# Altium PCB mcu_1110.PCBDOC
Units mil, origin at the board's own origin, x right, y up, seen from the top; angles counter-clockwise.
Board outline 4331.71 x 2363.2 mil, 2 copper layers (TOP, BOTTOM), stack 10.4 mil thick; 53 components, 41 nets, 250 pads, 209 vias.
Unrouted connection lines stored in the file: 59.
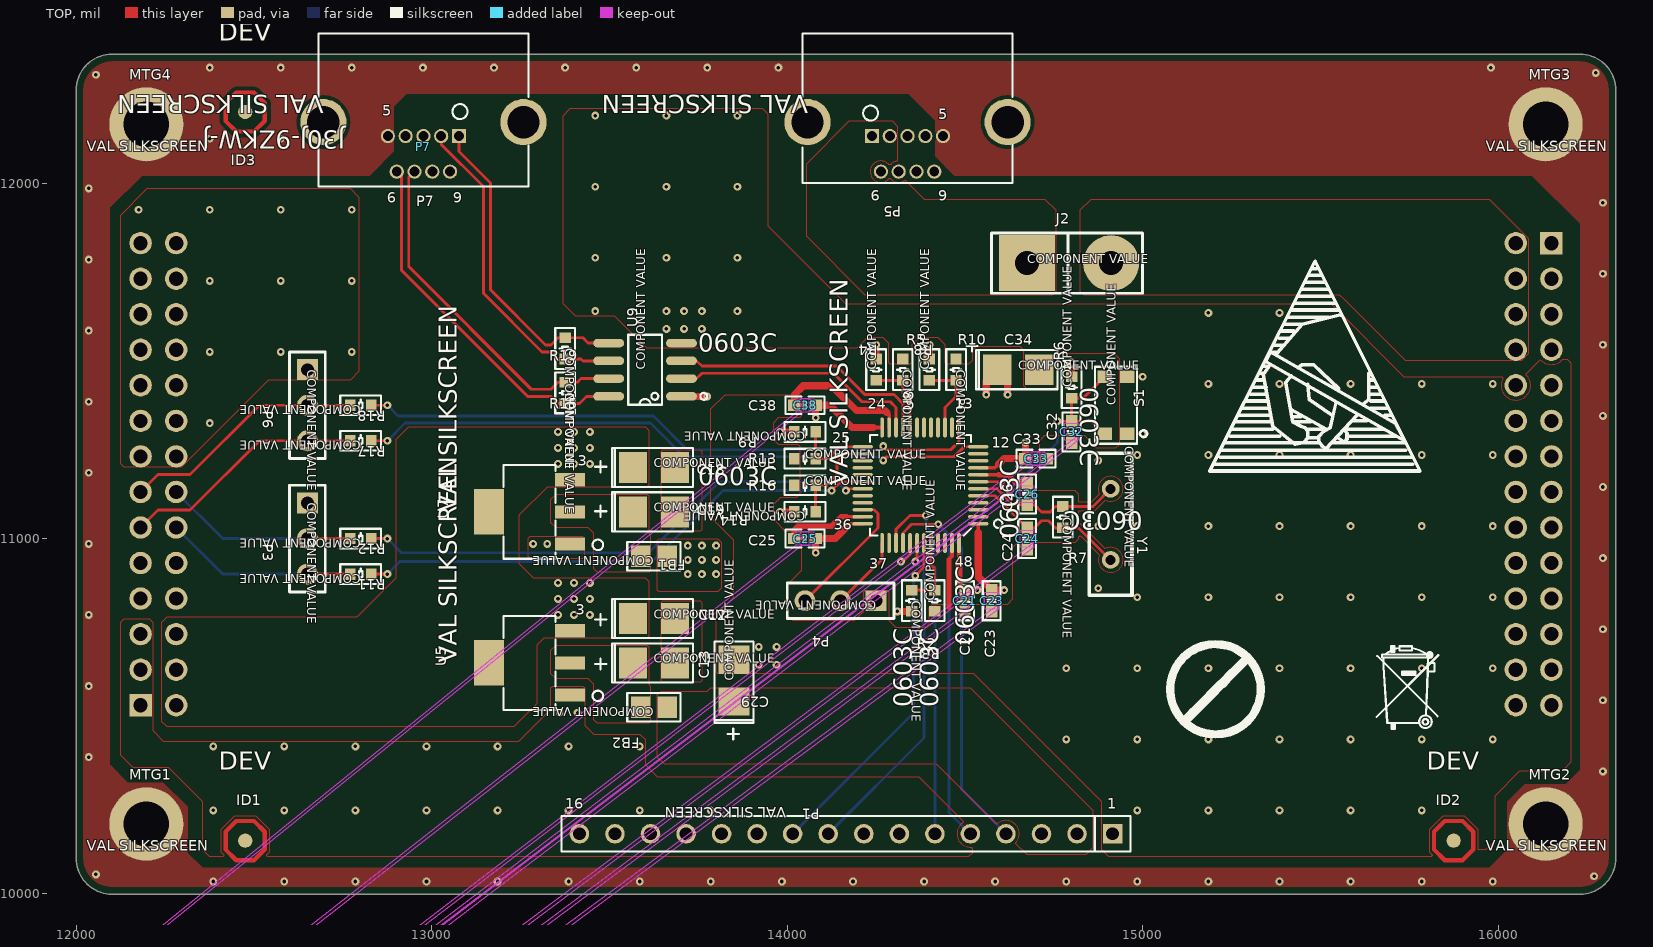
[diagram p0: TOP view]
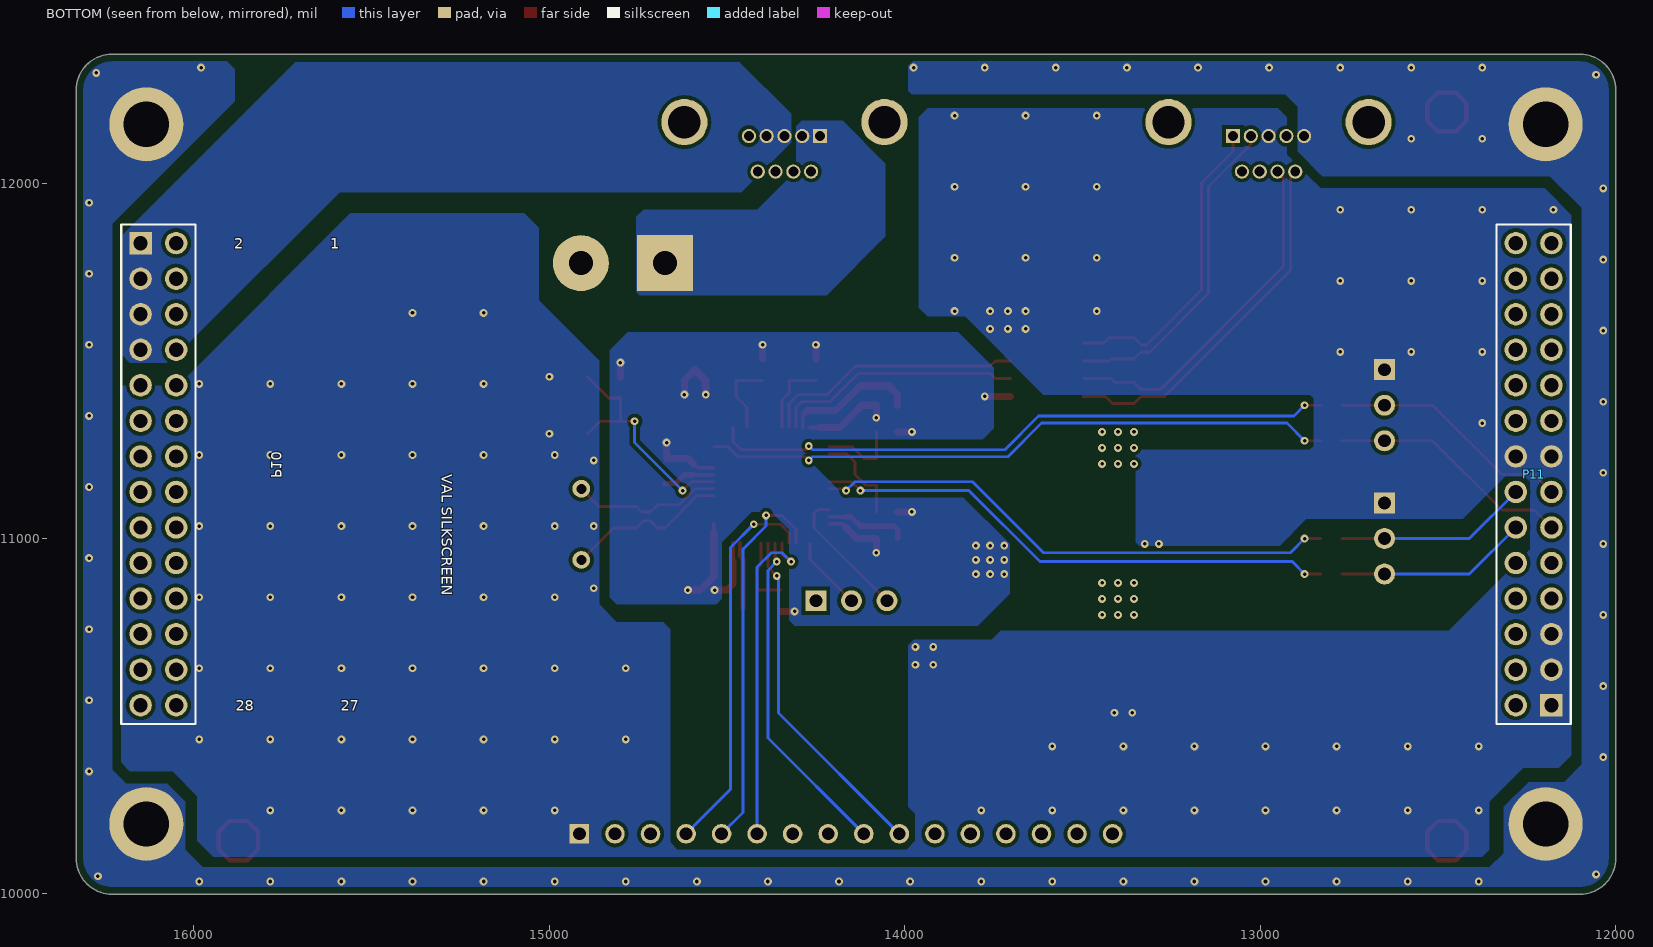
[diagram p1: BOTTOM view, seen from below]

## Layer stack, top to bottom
TOP: signal copper 1.2
Dielectric: core 8, FR-4, Dk 4.5
BOTTOM: signal copper 1.2

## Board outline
11999.5,10100 ccw(c12100,10100) 12100,9999.5 16230.71,9999.5 ccw(c16230.71,10100) 16331.21,10100 16331.21,12262.2 ccw(c16230.71,12262.2) 16230.71,12362.7 12100,12362.7 ccw(c12100,12262.2) 11999.5,12262.2

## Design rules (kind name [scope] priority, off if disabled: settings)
Clearance [All] p1: gap=10
PlaneConnect [All] p1: planeconnectstyle=Direct reliefexpansion=20 reliefentries=4 reliefconductorwidth=10 reliefairgap=10
PolygonConnect [All] p1: connectstyle=Direct reliefconductorwidth=10 reliefentries=4 polygonreliefangle="90 Angle"
RoomDefinition CompsKeepin1 [All vs False] p1: confinementstyle=ConfineIn formatcopy=TRUE lockcomponents=FALSE outline 12100,10040 12094.77,10040.23 12089.58,10040.91 12084.47,10042.04 12079.48,10043.62 12074.64,10045.62 12070,10048.04 12065.59,10050.85 12061.43,10054.04 12057.57,10057.57 12054.04,10061.43 12050.85,10065.59 12048.04,10070 12045.62,10074.64 12043.62,10079.48 12042.04,10084.47 12040.91,10089.58 12040.23,10094.77 12040,10100 12040,12262.2 12040.23,12267.43 12040.91,12272.62 12042.04,12277.73 12043.62,12282.73 12045.62,12287.56 12048.04,12292.2 12050.85,12296.62 12054.04,12300.77 12057.57,12304.63 12061.43,12308.17 12065.59,12311.35 12070,12314.17 12074.64,12316.58 12079.48,12318.59 12084.47,12320.16 12089.58,12321.29 12094.77,12321.98 12100,12322.2 16230.71,12322.2 16235.94,12321.98 16241.13,12321.29 16246.24,12320.16 16251.23,12318.59 16256.07,12316.58 16260.71,12314.17 16265.12,12311.35 16269.28,12308.17 16273.14,12304.63 16276.67,12300.77 16279.86,12296.62 16282.67,12292.2 16285.09,12287.56 16287.09,12282.73 16288.66,12277.73 16289.8,12272.62 16290.48,12267.43 16290.71,12262.2 16290.71,10100 16290.48,10094.77 16289.8,10089.58 16288.66,10084.47 16287.09,10079.48 16285.09,10074.64 16282.67,10070 16279.86,10065.59 16276.67,10061.43 16273.14,10057.57 16269.28,10054.04 16265.12,10050.85 16260.71,10048.04 16256.07,10045.62 16251.23,10043.62 16246.24,10042.04 16241.13,10040.91 16235.94,10040.23 16230.71,10040 12100,10040
RoutingVias [All] p1: holewidth=28 width=50 viastyle="Through Hole" minholewidth=28 minwidth=50 maxholewidth=28 maxwidth=50
SilkscreenOverComponentPads [All] p1: minsilkscreentomaskgap=10
SolderMaskExpansion [All] p1: expansion=4
TestPointUsage [All] p1: valid=0 allowmultiple=FALSE
Testpoint [All] p1: side=15 testpointundercomponent=TRUE minsize=40 maxsize=100 preferedsize=60 minholesize=0 maxholesize=40 preferedholesize=32 testpointgrid=1 style=1023 order=0123456789
Width [All] p1: maxlimit=10 minlimit=10 preferedwidth=10 impedancedriven=TRUE minimp=4.390000 maximp=4.390000 favimp=4.390000
22 further rules are at their usual default settings.

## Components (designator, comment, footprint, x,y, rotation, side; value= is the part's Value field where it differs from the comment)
C12 "3528T" 3528T 13607.28,10788.78 r0 top
C13 "3528T" 3528T 13607.28,10663.78 r0 top
C18 "3528T" 3528T 13607.28,11213.78 r0 top
C19 "3528T" 3528T 13607.28,11088.78 r0 top
C21 "0603C" 0603C#1 14500,10825 r90 top
C23 "0603C" 0603C#1 14575,10825 r90 top
C24 "0603C" 0603C#1 14675,11000 r90 top
C25 "0603C" 0603C#1 14050,11000 r0 top
C26 "0603C" 0603C#2 14675,11125 r270 top
C29 "3528T" 3528T 13836.22,10582.29 r90 top
C32 "0603C" 0603C#1 14800,11300 r90 top
C33 "0603C" 0603C#3 14700,11225 r180 top
C34 "3528T" 3528T 14632.28,11488.78 r0 top
C38 "0603C" 0603C#1 14050,11375 r0 top
FB1 "SM-7351-IND-0805" SM-7351-IND-0805 13625,10950 r180 top
FB2 "SM-7351-IND-0805" SM-7351-IND-0805 13625,10525 r180 top
J2 "28V" 28V 14787.5,11775 r0 top
MTG1 "MTGH200C125D_PL" MTGH200C125D_PL 12196.85,10196.85 r0 top
MTG2 "MTGH200C125D_PL" MTGH200C125D_PL 16133.86,10196.85 r0 top
MTG3 "MTGH200C125D_PL" MTGH200C125D_PL 16133.86,12165.35 r0 top
MTG4 "MTGH200C125D_PL" MTGH200C125D_PL 12196.85,12165.35 r0 top
P1 "HDR_16PIN" HDR_16PIN 14165.35,10169.29 r180 top
P3 "HDR1X3" HDR1X3 12650,11000 r270 top
P4 "HDR1X3" HDR1X3 14150,10825 r180 top
P5 "J30J-9TJW-J" J30J-9TJW-J 14338.75,12174.33 r180 top
P6 "HDR1X3" HDR1X3 12650,11375 r270 top
P7 "J30J-9ZKW-J" J30J-9ZKW-J 12976.55,12174.33 r180 top
P10 "HDR_14X2" HDR_14X2 16100.79,11181.5 r90 bottom
P11 "HDR_14X2" HDR_14X2 12229.92,11180.71 r270 bottom
R2 "R0603" R0603 14350,10825 r270 top
R3 "R0603" R0603 14415,10825 r90 top
R4 "R0603" R0603 14250,11475 r90 top
R5 "R0603" R0603 14325,11475 r270 top
R6 "R0603" R0603 14800,11425 r90 top
R7 "R0603" R0603 14775,11060 r270 top
R8 "R0603" R0603 14400,11475 r90 top
R9 "R0603" R0603 14050,11300 r180 top
R10 "R0603" R0603 14475,11475 r270 top
R11 "R0603" R0603 12800,10900 r180 top
R12 "R0603" R0603 12800,11000 r180 top
R13 "R0603" R0603 14050,11225 r0 top
R14 "R0603" R0603 14050,11075 r180 top
R15 "R0603" R0603 13375,11410 r270 top
R16 "R0603" R0603 14050,11150 r0 top
R17 "R0603" R0603 12800,11275 r180 top
R18 "R0603" R0603 12800,11375 r180 top
R19 "R0603" R0603 13375,11535 r270 top
S1 "SW4SMD_63X161LS" SW4SMD_63X161LS 14939.47,11375 r90 top
U5 "SOT-223-DCY" SOT-223-DCY 13272.58,10650.82 r90 top
U7 "SOT-223-DCY" SOT-223-DCY 13272.58,11075.82 r90 top
U8 "LQFP-48PIN" LQFP-48PIN 14375,11150 r90 top
U9 "8_SO" 8_SO 13630.52,11475 r90 top
Y1 "XTAL1" XTAL1 14910,11050 r270 top

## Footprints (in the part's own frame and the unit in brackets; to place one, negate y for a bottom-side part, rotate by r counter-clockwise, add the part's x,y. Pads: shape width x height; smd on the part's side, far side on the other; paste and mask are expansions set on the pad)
8_SO [mil] "8_SO"
  oval 24x87 smd: 1(-75,-71.84) 2(-25,-71.84) 3(25,-71.84) 4(75,-71.84) 5(75,132.87) 6(25,132.87) 7(-25,132.87) 8(-75,132.87)
  silkscreen extent -98,-145 98,78
28V [mil] "28V"
  rect 157x157 hole 67: 1(-112.5,0)
  round 157 hole 67: 2(123.72,0)
  silkscreen extent -212,-85 212,85
0603C#1 [mil] "0603C"
  rect 35x32 smd: 1(-30,0) 2(30,0)
  TOP keep-out region: -24,-19 -24,19 24,19 24,-19 -24,-19 -10825,14500
  TOP keep-out region: -10,-20 -10,20 10,20 10,-20 -10,-20 -10825,14500
  silkscreen extent -55,-25 55,25
0603C#2 [mil] "0603C"
  rect 35x32 smd: 1(-30,0) 2(30,0)
  TOP keep-out region: -24,-19 -24,19 24,19 24,-19 -24,-19 11125,-14675
  TOP keep-out region: -10,-20 -10,20 10,20 10,-20 -10,-20 11125,-14675
  silkscreen extent -55,-25 55,25
0603C#3 [mil] "0603C"
  rect 35x32 smd: 1(-30,0) 2(30,0)
  TOP keep-out region: -24,-19 -24,19 24,19 24,-19 -24,-19 14700,11225
  TOP keep-out region: -10,-20 -10,20 10,20 10,-20 -10,-20 14700,11225
  silkscreen extent -55,-25 55,25
3528T [mil] "3528T"
  rect 79x87 smd: 1(-41.34,-13.78) 2(76.77,-13.78)
  silkscreen extent -148,-69 128,41
HDR1X3 [mil] "HDR1X3"
  rect 59x59 hole 36: 1(-100,0)
  round 59 hole 36: 2(0,0) 3(100,0)
  silkscreen extent -150,-50 150,50
HDR_14X2 [mil] "HDR_14X2"
  rect 63x63 hole 40: 1(649.61,49.21)
  round 63 hole 40: 2(649.61,-50.79) 3(549.61,49.21) 4(549.61,-50.79) 5(449.61,49.21) 6(449.61,-50.79) 7(349.61,49.21) 8(349.61,-50.79) 9(249.61,49.21) 10(249.61,-50.79) 11(149.61,49.21) 12(149.61,-50.79) 13(49.61,49.21) 14(49.61,-50.79) 15(-50.39,49.21) 16(-50.39,-50.79) 17(-150.39,49.21) 18(-150.39,-50.79) 19(-250.39,49.21) 20(-250.39,-50.79) 21(-350.39,49.21) 22(-350.39,-50.79) 23(-450.39,49.21) 24(-450.39,-50.79) 25(-550.39,49.21) 26(-550.39,-50.79) 27(-650.39,49.21) 28(-650.39,-50.79)
  silkscreen extent -703,-105 702,104
HDR_16PIN [mil] "HDR_16PIN"
  rect 55x55 hole 36: 1(-750,0)
  round 55 hole 36: 2(-650,0) 3(-550,0) 4(-450,0) 5(-350,0) 6(-250,0) 7(-150,0) 8(-50,0) 9(50,0) 10(150,0) 11(250,0) 12(350,0) 13(450,0) 14(550,0) 15(650,0) 16(750,0)
  silkscreen extent -800,-50 800,50
J30J-9TJW-J [mil] "J30J-9TJW-J"
  rect 40x40 hole 28: 1(100.17,42.05)
  round 40 hole 28: 2(50.17,42.05) 3(0.17,42.05) 4(-49.83,42.05) 5(-99.83,42.05) 6(75.17,142.05) 7(25.17,142.05) 8(-24.83,142.05) 9(-74.83,142.05)
  round 130 hole 91: 10(281.67,2.67) 11(-281.33,2.67)
  silkscreen extent -295,-247 295,173
J30J-9ZKW-J [mil] "J30J-9ZKW-J"
  rect 40x40 hole 28: 1(-99.83,42.04)
  round 40 hole 28: 2(-49.83,42.04) 3(0.17,42.04) 4(50.17,42.04) 5(100.17,42.04) 6(-74.83,142.04) 7(-24.83,142.04) 8(25.17,142.04) 9(75.17,142.04)
  round 130 hole 91: 10(281.67,2.67) 11(-281.33,2.67)
  silkscreen extent -295,-247 295,183
LQFP-48PIN [mil] "LQFP-48PIN"
  oval 10x57 smd: 1(-108.27,-162.4) 2(-88.58,-162.4) 3(-68.9,-162.4) 4(-49.21,-162.4) 5(-29.53,-162.4) 6(-9.84,-162.4) 7(9.84,-162.4) 8(29.53,-162.4) 9(49.21,-162.4) 10(68.9,-162.4) 11(88.58,-162.4) 12(108.27,-162.4) 25(108.27,162.4) 26(88.58,162.4) 27(68.9,162.4) 28(49.21,162.4) 29(29.53,162.4) 30(9.84,162.4) 31(-9.84,162.4) 32(-29.53,162.4) 33(-49.21,162.4) 34(-68.9,162.4) 35(-88.58,162.4) 36(-108.27,162.4)
  oval 57x10 smd: 13(162.4,-108.27) 14(162.4,-88.58) 15(162.4,-68.9) 16(162.4,-49.21) 17(162.4,-29.53) 18(162.4,-9.84) 19(162.4,9.84) 20(162.4,29.53) 21(162.4,49.21) 22(162.4,68.9) 23(162.4,88.58) 24(162.4,108.27) 37(-162.4,108.27) 38(-162.4,88.58) 39(-162.4,68.9) 40(-162.4,49.21) 41(-162.4,29.53) 42(-162.4,9.84) 43(-162.4,-9.84) 44(-162.4,-29.53) 45(-162.4,-49.21) 46(-162.4,-68.9) 47(-162.4,-88.58) 48(-162.4,-108.27)
  silkscreen extent -142,-230 142,142
MTGH200C125D_PL [mil] "MTGH200C125D_PL"
  round 208 hole 128: 1(0,0)
R0603 [mil] "R0603"
  rect 30x32 smd: 1(-29.92,0) 2(29.92,0)
  silkscreen extent -57,-28 57,28
SM-7351-IND-0805 [mil] "SM-7351-IND-0805"
  rect 55x61 smd: 1(37.4,0) 2(-37.4,0)
  silkscreen extent -75,-40 75,40
SOT-223-DCY [mil] "SOT-223-DCY"
  rect 37x85 smd: 1(-91.37,-116.58) 2(-0.82,-116.58) 3(89.73,-116.58)
  rect 128x85 smd: 4(-0.82,111.75)
  silkscreen extent -133,-209 131,70
SW4SMD_63X161LS [mil] "SW4SMD_63X161LS"
  rect 35x40 smd: 1(-80.71,-17.03) 2(-80.71,45.97) 3(80.71,-17.03) 4(80.71,45.97)
  silkscreen extent -108,-74 108,74
XTAL1 [mil] "XTAL1"
  round 50 hole 28: 1(-90,0) 2(110,0)
  silkscreen extent -190,-60 210,60

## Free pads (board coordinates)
  round 40 smd: 1(12475,10150) 1(12475,12200) 1(15875,10150)

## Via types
v1: diameter 22, hole 10, TOP to BOTTOM, 209 vias

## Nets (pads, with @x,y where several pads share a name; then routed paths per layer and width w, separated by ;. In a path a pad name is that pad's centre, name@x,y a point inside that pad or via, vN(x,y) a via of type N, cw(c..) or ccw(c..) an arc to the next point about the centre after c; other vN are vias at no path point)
+3V3: C21.2 C23.2 C25.2 C33.2 C34.1 C38.2 FB1.2 R2.2 R4.2 R6.2 R8.2 R9.2 R14.2 U8.1 U8.9 U8.24 U8.36 U8.48 U9.1 | length 1515.6
  TOP w10: 14166.73,11031.73 14176.73,11041.73 U8.36 ; 14242.6,11312.4 U8.24 ; 14483.27,10935 U8.48 ; 14537.4,11017.4 U8.1 ; U8.9 14584.21,11199.21 14595,11210
  TOP w20: U9.1 v1(13775,11400) ; v1(13980,11075) R14.2 ; v1(13980,11300) R9.2 ; v1(14080,10960) C25.2 14135,11000 14166.73,11031.73 ; v1(14080,11340) C38.2 14120,11375 14182.6,11312.4 14242.6,11312.4 ; R4.2 v1(14250,11545) ; v1(14310,10795) 14349.92,10795 R2.2 ; R8.2 v1(14400,11545) ; 14483.27,10935 14483.27,10871.73 C21.2 v1(14535,10855) ; 14537.4,11017.4 14537.4,10892.6 C23.2 v1(14610,10855) ; v1(14560,11405) 14560,11444.06 C34.1 14620,11445.94 v1(14620,11405) ; 14595,11210 14610,11225 C33.2 v1(14670,11270) ; R6.2 v1(14800,11495)
  other v1: 13720,10900 13760,10900 13800,10900 13720,10940 13760,10940 13800,10940 13720,10980 13760,10980 13800,10980
BOOT0: R2.1 R3.2 U8.44 | length 202
  TOP w8: R2.1 R3.2 14415,10915 14404.53,10925.47 U8.44
EARTH: MTG1.1 MTG2.1 MTG3.1 MTG4.1 P5.5 P7.5
  other v1: 12385,10035 12585,10035 12785,10035 12985,10035 13185,10035 13385,10035 13585,10035 13785,10035 13985,10035 14185,10035 14385,10035 14585,10035 14785,10035 14985,10035 15185,10035 15385,10035 15585,10035 15785,10035 15985,10035 16270,10050 12055,10055 16295,10345 12035,10385 16295,10545 12035,10585 16295,10745 12035,10785 16295,10945 12035,10985 16295,11145 12035,11185 16295,11345 12035,11385 16295,11545 12035,11585 16295,11745 12035,11785 16295,11945 12035,11985 12375,12125 12575,12125 12055,12305 16275,12310 12375,12325 12575,12325 12775,12325 12975,12325 13175,12325 13375,12325 13575,12325 13775,12325 13975,12325 15980,12325
GND: C21.1 C23.1 C24.1 C25.1 C26.1 C29.2 C32.1 C33.1 C34.2 C38.1 P1.1 P3.1 P4.1 P6.1 P7.3 P11.1 P11.3 P11.5 P11.15 P11.16 R3.1 R5.1 R10.1 R13.1 R16.1 S1.1 S1.3 U5.1 U7.1 U8.8 U8.23 U8.35 U8.47 U9.4 | length 943.3
  TOP w10: 14166.42,11061.42 U8.35 ; 14280,11355 14286.42,11348.58 U8.23 ; 14455,10940 14455,10941.42 14463.58,10950 U8.47 ; U8.8 14594.53,11179.53
  TOP w15: C25.1 14020,11025 14030,11035 14125,11035 14151.42,11061.42 14166.42,11061.42 ; 14455,10805 14455,10930 14455,10940 ; 14594.53,11179.53 14620.47,11179.53 14645,11155 C26.1
  TOP w20: C38.1 14020,11405 14045,11430 14125,11430 14195,11360 14275,11360 14280,11355
  other v1: 12385,10235 12585,10235 12785,10235 12985,10235 13185,10235 13385,10235 13585,10235 13785,10235 14985,10235 15185,10235 15385,10235 15585,10235 15785,10235 12385,10415 12585,10415 12785,10415 12985,10415 13185,10415 13385,10415 13585,10415 14785,10435 14985,10435 15185,10435 15385,10435 15585,10435 15785,10435 15985,10435 13360,10510 13410,10510 14785,10635 14985,10635 15185,10635 15385,10635 15585,10635 15785,10635 15985,10635 13920,10645 13970,10645 13920,10695 13970,10695 14985,10835 15185,10835 15385,10835 15585,10835 15785,10835 15985,10835 14875,10860 13285,10985 13325,10985 14875,11035 14985,11035 15185,11035 15385,11035 15585,11035 15785,11035 15985,11035 14875,11220 14985,11235 15185,11235 15385,11235 15585,11235 15785,11235 15985,11235 15000,11295 12375,11325 15185,11435 15385,11435 15585,11435 15785,11435 15985,11435 15000,11455 12375,11525 12575,11525 12775,11525 13660,11590 13710,11590 13760,11590 15185,11635 15385,11635 13460,11640 13660,11640 13710,11640 13760,11640 13860,11640 12375,11725 12575,11725 12775,11725 13460,11790 13660,11790 13860,11790 12175,11925 12375,11925 12575,11925 12775,11925 13460,11990 13660,11990 13860,11990 13460,12190 13660,12190 13860,12190
NETC12_2: C12.2 C13.2
NETC18_2: C18.2 C19.2
NETP7_1: P7.1 R19.1 U9.5 | length 880.3
  TOP w8: P7.1 13076.38,12088.62 13165,12000 13165,11700 13320,11545 13335,11545 13354.92,11564.92 R19.1 13425,11564.92 13439.92,11550 U9.5
NETP7_2: P7.2 R19.2 U9.6 | length 922.8
  TOP w8: P7.2 13026.38,12108.62 13145,11990 13145,11690 13310,11525 13335,11525 13354.92,11505.08 R19.2 13419.92,11505.08 13425,11500 U9.6
NETP7_8: P7.8 R15.1 U9.7 | length 992
  TOP w8: P7.8 12935,12015.91 12935,11765 13280,11420 13335,11420 13354.92,11439.92 R15.1 13409.92,11439.92 13420,11450 U9.7
NETP7_9: P7.9 R15.2 U9.8 | length 1029.1
  TOP w8: P7.9 12915,12018.66 12915,11755 13270,11400 13335.08,11400 13355,11380.08 R15.2 13415.08,11380.08 13435,11400 U9.8
NRST: C32.2 R6.1 S1.2 S1.4 U8.7 | length 680.8
  TOP w8: U8.7 14600.16,11159.84 v1(14625,11135) ; v1(14760,11330) C32.2 ; S1.2 14857.79,11330 C32.2 ; S1.4 14832.87,11395.08 R6.1 C32.2
  BOTTOM w8: v1(14625,11135) 14760,11270 v1(14760,11330)
OLED_3V3: C29.1 FB2.2 P1.2
OLED_CS: P1.5 U8.39 | length 1086.1
  TOP w8: U8.39 14306.1,11026.1 14345,11065 v1(14390,11065)
  BOTTOM w8: v1(14390,11065) 14390,11035 14455,10970 14455,10229.65 P1.5
OLED_DC: P1.6 U8.41 | length 938.9
  TOP w8: v1(14320,10935) 14325,10935 14345.47,10955.47 U8.41
  BOTTOM w8: v1(14320,10935) 14345,10960 14375,10960 14415.35,10919.65 P1.6
OLED_RST: P1.4 U8.40 | length 1087
  TOP w8: U8.40 14325.79,11015.79 14350,11040 v1(14425,11040)
  BOTTOM w8: v1(14425,11040) 14490,10975 14490,10294.65 P1.4
OLED_SCLK: P1.9 U8.42 | length 942.5
  TOP w8: v1(14360,10935) 14365.16,10940.16 U8.42
  BOTTOM w8: P1.9 14385,10438.94 14385,10910 v1(14360,10935)
OLED_SDIN: P1.10 U8.43 | length 971.4
  TOP w8: v1(14360,10895) 14384.84,10919.84 U8.43
  BOTTOM w8: P1.10 14355,10508.94 14355,10890 v1(14360,10895)
PA5: R8.1 R10.2 U8.15 | length 220.6
  TOP w8: R8.1 R10.2 14475,11400 14443.9,11368.9 U8.15
PB2: R4.1 R5.2 U8.20 | length 216.2
  TOP w8: R4.1 R5.2 14325,11410 14345.47,11389.53 U8.20
PB12: R9.1 R13.2 U8.25 | length 221.5
  TOP w8: R9.1 R13.2 14115,11225 14148.27,11258.27 U8.25
PB13: R14.1 R16.2 U8.26 | length 264.9
  TOP w8: R14.1 R16.2 14110,11150 14140,11180 14140,11215 14163.58,11238.58 U8.26
PD0: C24.2 R7.2 U8.5 Y1.2 | length 463.9
  TOP w8: U8.5 14584.53,11120.47 C24.2 14695,11030 14715,11050 14735,11050 14754.92,11030.08 R7.2 14819.92,11030.08 Y1.2
PD1: C26.2 R7.1 U8.6 Y1.1 | length 426.5
  TOP w8: U8.6 14589.84,11140.16 14635,11095 C26.2 14695,11095 14715,11075 14740,11075 14754.92,11089.92 R7.1 14859.92,11089.92 Y1.1
RX_BD: P6.3 P11.11 R17.2 | length 690.4
  TOP w8: P11.11 12229.61,11080 12320,11080 12515,11275 P6.3 R17.2
RX_GPS: P3.3 P11.12 R11.2 | length 543.7
  TOP w8: P3.3 R11.2
  BOTTOM w8: P11.12 12411.81,10900 P3.3
SWCLK: P4.2 U8.37 | length 210.9
  TOP w8: P4.2 14266.73,10941.73 U8.37
SWDIO: P4.3 U8.34 | length 376.9
  TOP w8: P4.3 14255,11030 14255,11070 14243.9,11081.1 U8.34
TX_BD: P6.2 P11.13 R18.2 | length 690.4
  TOP w8: P11.13 12229.61,11180 12320,11180 12515,11375 P6.2 R18.2
TX_GPS: P3.2 P11.14 R12.2 | length 543.7
  TOP w8: P3.2 R12.2
  BOTTOM w8: P11.14 12411.81,11000 P3.2
UART1_RX: R12.1 U8.31 | length 1494.6
  TOP w8: R12.1 v1(12875,11000) ; v1(14165,11135) 14170.16,11140.16 U8.31
  BOTTOM w8: v1(12875,11000) 12915,10960 13609.64,10960 13809.64,11160 14140,11160 v1(14165,11135)
UART1_TX: R11.1 U8.30 | length 1490.3
  TOP w8: R11.1 v1(12875,10900) ; v1(14125,11135) 14149.84,11159.84 U8.30
  BOTTOM w8: v1(12875,10900) 12910,10935 13620,10935 13820,11135 v1(14125,11135)
UART2_RX: R18.1 U8.13 | length 1762.2
  TOP w8: R18.1 v1(12875,11375) ; v1(14270,11260) 14280,11250 14460,11250 14483.27,11273.27 U8.13
  BOTTOM w8: v1(12875,11375) 12905,11345 13623.28,11345 13718.28,11250 14260,11250 v1(14270,11260)
UART2_TX: R17.1 U8.12 | length 1787.5
  TOP w8: R17.1 v1(12875,11275) ; v1(14270,11220) 14280,11230 14470,11230 14498.27,11258.27 U8.12
  BOTTOM w8: v1(12875,11275) 12925,11325 13615,11325 13710,11230 14260,11230 v1(14270,11220)
UART3_RX: U8.22 U9.2 | length 706.3
  TOP w8: U9.2 13745,11450 13760,11465 14130,11465 14210,11385 14290,11385 14306.1,11368.9 U8.22
UART3_TX: U8.21 U9.3 | length 740.3
  TOP w8: U9.3 13745,11500 13760,11485 14138.29,11485 14218.28,11405 14300,11405 14325.79,11379.21 U8.21
VBUS+: J2.1 P5.1 P5.2
VBUS-: P5.3 P5.4 P10.1 P10.3 P10.5 P10.7
VBUSXX+: J2.2 P10.2 P10.4 P10.6 P10.8
VDD_3V3_1: C19.1 FB1.1 U7.2
VDD_3V3_2: C13.1 FB2.1 U5.2
VDD_12V: C12.1 C18.1 P11.2 P11.4 P11.6 U5.3 U7.3
  other v1: 13355,10785 13400,10785 13445,10785 13355,10830 13400,10830 13445,10830 13355,10875 13400,10875 13445,10875 13355,11210 13400,11210 13445,11210 13355,11255 13400,11255 13445,11255 13355,11300 13400,11300 13445,11300
pads on no net: P1.3 P1.7 P1.8 P1.11 P1.12 P1.13 P1.14 P1.15 P1.16 P5.6 P5.7 P5.8 P5.9 P5.10 P5.11 P7.4 P7.6 P7.7 P7.10 P7.11 P10.9 P10.10 P10.11 P10.12 P10.13 P10.14 P10.15 P10.16 P10.17 P10.18 P10.19 P10.20 P10.21 P10.22 P10.23 P10.24 P10.25 P10.26 P10.27 P10.28 P11.7 P11.8 P11.9 P11.10 P11.17 P11.18 P11.19 P11.20 P11.21 P11.22 P11.23 P11.24 P11.25 P11.26 P11.27 P11.28 U5.4 U7.4 U8.2 U8.3 U8.4 U8.10 U8.11 U8.14 U8.16 U8.17 U8.18 U8.19 U8.27 U8.28 U8.29 U8.32 U8.33 U8.38 U8.45 U8.46
copper on no net: | length 1109.1
  TOP w12: 12420,10125 12450,10095 12500,10095 12530,10125 12530,10175 12500,10205 12450,10205 12420,10175 12420,10125 ; 12420,12175 12450,12145 12500,12145 12530,12175 12530,12225 12500,12255 12450,12255 12420,12225 12420,12175 ; 15820,10125 15850,10095 15900,10095 15930,10125 15930,10175 15900,10205 15850,10205 15820,10175 15820,10125

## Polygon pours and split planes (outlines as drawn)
VDD_12V on TOP (solid): 26 vertices, not listed, extent 12240,10470 13610,11315
VDD_3V3_2 on TOP (solid): 13335,10620 13335,10685 13350,10700 13605,10700 13610,10695 13610,10590 13615,10585 13615,10485 13610,10480 13465,10480 13455,10490 13455,10590 13440,10605 13350,10605 13335,10620
VDD_3V3_1 on TOP (solid): 13335,11045 13335,11110 13350,11125 13605,11125 13610,11120 13610,11015 13615,11010 13615,10910 13610,10905 13465,10905 13455,10915 13455,11015 13440,11030 13350,11030 13335,11045
VBUSXX+ on TOP (solid): 16065,11500 15740,11500 15570,11670 15555,11685 14835,11685 14825,11695 14825,11925 14855,11955 15975,11955 16085,11845 16085,11520 16065,11500
VBUS+ on TOP (solid): 150 vertices, not listed, extent 14055,11685 14755,12175
OLED_3V3 on TOP (solid): 53 vertices, not listed, extent 13635,10110 14860,10580
NETC12_2 on TOP (solid): 13650,10825 13730,10825 13755,10825 13760,10820 13760,10600 13755,10595 13730,10595 13650,10595 13645,10600 13645,10820 13650,10825
NETC18_2 on TOP (solid): 13650,11250 13730,11250 13755,11250 13760,11245 13760,11025 13755,11020 13730,11020 13650,11020 13645,11025 13645,11245 13650,11250
GND on TOP (solid): 456 vertices, not listed, extent 13370,10105 16205,12210
GND on TOP (solid): 166 vertices, not listed, extent 12125,10105 14520,10775
GND on TOP (solid): 12125,11215 12125,11910 12200,11985 12660,11985 12770,11985 12795,11960 12795,11470 12770,11445 12710,11445 12540,11445 12295,11200 12160,11200 12135,11200 12125,11210 12125,11215
GND on TOP (solid): 13425,11005 13275,11005 13270,11000 13270,10950 13275,10945 13425,10945 13430,10950 13430,11000 13425,11005
+3V3 on TOP (solid): 13635,10855 13635,10995 13640,11000 13805,11000 13815,10990 13815,10860 13805,10850 13640,10850 13635,10855
EARTH on TOP (solid): 82 vertices, not listed, extent 12020,10020 16310.71,12342.2
VBUS+ on BOTTOM (solid): 137 vertices, not listed, extent 14055,11685 14755,12175
GND on BOTTOM (solid): 731 vertices, not listed, extent 12125,10105 16205,12210
+3V3 on BOTTOM (solid): 220 vertices, not listed, extent 13705,10755 14830,11580
EARTH on BOTTOM (solid): 110 vertices, not listed, extent 12020,10020 16310.71,12342.2
VBUS- on BOTTOM (solid): 159 vertices, not listed, extent 14320,11495 16200,12340
no net on Top Overlay (solid): 15343.11,10576.04 ccw(c15205.05,10576.04) 15205.05,10714.1 ccw(c15205.05,10576.04) 15066.98,10576.04 ccw(c15205.05,10576.04) 15205.05,10437.98 ccw(c15205.05,10576.04) 15343.11,10576.04
no net on Top Overlay (solid): 47 vertices, not listed, extent 15230.35,10516.09 15302.87,10640.37
no net on Top Overlay (solid): 33 vertices, not listed, extent 15119.06,10517.52 15212.4,10640.37
no net on Top Overlay (solid): 15343.11,10576.04 ccw(c15205.05,10576.04) 15205.05,10714.1 ccw(c15205.05,10576.04) 15066.98,10576.04 ccw(c15205.05,10576.04) 15205.05,10437.98 ccw(c15205.05,10576.04) 15343.11,10576.04
no net on Top Overlay (solid): 47 vertices, not listed, extent 15230.35,10516.09 15302.87,10640.37
no net on Top Overlay (solid): 33 vertices, not listed, extent 15119.06,10517.52 15212.4,10640.37

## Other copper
TOP:
  drawing of 49 lines, arcs and shapes, not listed
  text "MCU V1 ARTWORK TOP" at 13430,9595 h100
BOTTOM:
  drawing of 61 lines, arcs and shapes, not listed
  text "MCU V1 ARTWORK BOTTOM" at 15285,9590 h100

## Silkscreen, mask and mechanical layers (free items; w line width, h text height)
Top Overlay:
  drawing of 316 lines, arcs and shapes, not listed
  text "3" at 15747.01,21522.01 h125
  text "3" at 15747.01,21522.02 h125
  text "3" at 15747.01,21522.01 h125
  text "3" at 15747.01,21522.02 h125
  text "5" at 21396.61,21522.02 h125
  text "5" at 21396.61,21522.02 h125
  text "1" at 10116.41,21518.76 h125
  text "1" at 10116.41,21518.76 h125
  text "4" at 18567.2,21518.76 h125
  text "4" at 18567.2,21518.76 h125
  text "7" at 27049.48,21518.75 h125
  text "7" at 27049.48,21518.76 h125
  text "7" at 27049.48,21518.75 h125
  text "7" at 27049.48,21518.76 h125
  text "8" at 29974.28,21518.76 h125
  text "8" at 29974.28,21518.76 h125
  text "2" at 12922.74,21514.81 h125
  text "2" at 12922.74,21514.8 h125
  text "2" at 12922.74,21514.81 h125
  text "2" at 12922.74,21514.8 h125
  text "6" at 24225.48,21515.22 h125
  text "6" at 24225.48,21515.22 h125
  text "6" at 24225.48,21515.22 h125
  text "6" at 24225.48,21515.22 h125
  text "A" at 8574.09,20514.82 h125
  text "A" at 8574.09,20514.82 h125
  text "A" at 31369.36,20514.82 h125
  text "A" at 31369.36,20514.82 h125
  text "B" at 8581.96,18546.31 h125
  text "B" at 8581.96,18546.31 h125
  text "B" at 31377.24,18546.31 h125
  text "B" at 31377.24,18546.31 h125
  text "C" at 8593.5,16577.81 h125
  text "C" at 8593.5,16577.81 h125
  text "C" at 31388.78,16577.81 h125
  text "C" at 31388.78,16577.81 h125
  text "D" at 8577.48,14609.31 h125
  text "D" at 8577.48,14609.31 h125
  text "D" at 31372.75,14609.31 h125
  text "D" at 31372.75,14609.31 h125
  text "E" at 8589.83,12640.8 h125
  text "E" at 8589.83,12640.8 h125
  text "E" at 31385.11,12640.8 h125
  text "E" at 31385.11,12640.8 h125
  text "DEV" at 12400,12400 h51
  text "ID3" at 12435,12050 h30
  text "F" at 8589.83,10672.3 h125
  text "F" at 8589.83,10672.3 h125
  text "F" at 31385.11,10672.3 h125
  text "F" at 31385.11,10672.3 h125
  text "DEV" at 12400,10350 h51
  text "DEV" at 15800,10350 h51
  text "ID1" at 12450,10250 h30
  text "ID2" at 15825,10250 h30
  text "G" at 8586.04,8703.8 h125
  text "G" at 8586.04,8703.8 h125
  text "G" at 31381.31,8703.8 h125
  text "G" at 31381.31,8703.8 h125
  text "H" at 8581.96,6735.3 h125
  text "H" at 8581.96,6735.3 h125
  text "H" at 31377.24,6735.3 h125
  text "H" at 31377.24,6735.3 h125
  text "3" at 15747.01,5577.13 h125
  text "3" at 15747.01,5577.13 h125
  text "5" at 21396.61,5577.14 h125
  text "5" at 21396.61,5577.14 h125
  text "1" at 10116.41,5573.87 h125
  text "1" at 10116.41,5573.87 h125
  text "4" at 18567.2,5573.88 h125
  text "4" at 18567.2,5573.88 h125
  text "7" at 27049.48,5573.87 h125
  text "7" at 27049.48,5573.87 h125
  text "8" at 29874.28,5573.87 h125
  text "8" at 29874.28,5573.87 h125
  text "2" at 12922.74,5569.93 h125
  text "2" at 12922.74,5569.93 h125
  text "6" at 24225.48,5570.34 h125
  text "6" at 24225.48,5570.34 h125
Bottom Overlay:
  drawing of 13290 lines, arcs and shapes, not listed
  text "8" at 10033,21537.5 h125
  text "8" at 10033,21537.5 h125
  text "5" at 18682.66,21531.02 h125
  text "5" at 18682.66,21531.02 h125
  text "3" at 24332.26,21531.02 h125
  text "3" at 24332.26,21531.02 h125
  text "7" at 13029.79,21527.76 h125
  text "7" at 13029.79,21527.76 h125
  text "4" at 21512.07,21527.76 h125
  text "4" at 21512.07,21527.76 h125
  text "1" at 29962.86,21527.76 h125
  text "1" at 29962.86,21527.76 h125
  text "6" at 15853.79,21524.22 h125
  text "6" at 15853.79,21524.22 h125
  text "2" at 27156.53,21523.8 h125
  text "2" at 27156.53,21523.8 h125
  text "A" at 8709.91,20523.82 h125
  text "A" at 8709.91,20523.82 h125
  text "A" at 31505.18,20523.82 h125
  text "A" at 31505.18,20523.82 h125
  text "B" at 8702.03,18555.31 h125
  text "B" at 8702.03,18555.31 h125
  text "B" at 31497.31,18555.31 h125
  text "B" at 31497.31,18555.31 h125
  text "C" at 8690.49,16586.81 h125
  text "C" at 8690.49,16586.81 h125
  text "C" at 31485.77,16586.81 h125
  text "C" at 31485.77,16586.81 h125
  text "D" at 8706.52,14618.31 h125
  text "D" at 8706.52,14618.31 h125
  text "D" at 31501.79,14618.31 h125
  text "D" at 31501.79,14618.31 h125
  text "E" at 8694.16,12649.8 h125
  text "E" at 8694.16,12649.8 h125
  text "E" at 31489.44,12649.8 h125
  text "E" at 31489.44,12649.8 h125
  text "F" at 8694.16,10681.3 h125
  text "F" at 8694.16,10681.3 h125
  text "F" at 31489.44,10681.3 h125
  text "F" at 31489.44,10681.3 h125
  text "G" at 8697.96,8712.8 h125
  text "G" at 8697.96,8712.8 h125
  text "G" at 31493.23,8712.8 h125
  text "G" at 31493.23,8712.8 h125
  text "H" at 8702.03,6744.3 h125
  text "H" at 8702.03,6744.3 h125
  text "H" at 31497.31,6744.3 h125
  text "H" at 31497.31,6744.3 h125
  text "5" at 18682.66,5586.14 h125
  text "5" at 18682.66,5586.14 h125
  text "3" at 24332.26,5586.13 h125
  text "3" at 24332.26,5586.13 h125
  text "8" at 10204.99,5582.87 h125
  text "8" at 10204.99,5582.87 h125
  text "7" at 13029.79,5582.87 h125
  text "7" at 13029.79,5582.87 h125
  text "4" at 21512.07,5582.88 h125
  text "4" at 21512.07,5582.88 h125
  text "1" at 29962.86,5582.87 h125
  text "1" at 29962.86,5582.87 h125
  text "6" at 15853.79,5579.34 h125
  text "6" at 15853.79,5579.34 h125
  text "2" at 27156.53,5578.93 h125
  text "2" at 27156.53,5578.93 h125
DIMENSION:
  drawing of 8561 lines, arcs and shapes, not listed
  text "3" at 15747.01,21522.01 h125
  text "3" at 15747.01,21522.02 h125
  text "3" at 15747.01,21522.01 h125
  text "3" at 15747.01,21522.02 h125
  text "5" at 21396.61,21522.02 h125
  text "5" at 21396.61,21522.02 h125
  text "1" at 10116.41,21518.76 h125
  text "1" at 10116.41,21518.76 h125
  text "4" at 18567.2,21518.76 h125
  text "4" at 18567.2,21518.76 h125
  text "7" at 27049.48,21518.75 h125
  text "7" at 27049.48,21518.76 h125
  text "7" at 27049.48,21518.75 h125
  text "7" at 27049.48,21518.76 h125
  text "8" at 29974.28,21518.76 h125
  text "8" at 29974.28,21518.76 h125
  text "2" at 12922.74,21514.81 h125
  text "2" at 12922.74,21514.8 h125
  text "2" at 12922.74,21514.81 h125
  text "2" at 12922.74,21514.8 h125
  text "6" at 24225.48,21515.22 h125
  text "6" at 24225.48,21515.22 h125
  text "6" at 24225.48,21515.22 h125
  text "6" at 24225.48,21515.22 h125
  text "A" at 8574.09,20514.82 h125
  text "A" at 8574.09,20514.82 h125
  text "A" at 31369.36,20514.82 h125
  text "A" at 31369.36,20514.82 h125
  text "BOARD NAME:" at 24938.5,20505.5 h75
  text "BOARD LAYERS:" at 27438.5,20505.5 h75
  text "BOARD THICKNESS:" at 24938.5,20305.5 h75
  text "MM +/-10%" at 26513.5,20305.5 h75
  text "SOLDER MASK: IPC SM-840" at 27438.5,20305.5 h75
  text "SOLDER COLORS:" at 24938.5,20105.5 h75
  text "GREEN" at 26538.5,20105.5 h75
  text "RED" at 27548.5,20105.5 h75
  text "YELLOW" at 28258.5,20105.5 h75
  text "OTHER" at 29238.5,20105.5 h75
  text "SILKSCREEN COLORS:" at 24938.5,19905.5 h75
  text "WHITE" at 26538.5,19905.5 h75
  text "RED" at 27548.5,19905.5 h75
  text "YELLOW" at 28258.5,19905.5 h75
  text "OTHER" at 29238.5,19905.5 h75
  text "HASL(Sn/Pb)" at 26358.5,19705.5 h75
  text "IMMERSION GOLD" at 27718.5,19705.5 h75
  text "OSP" at 29298.5,19705.5 h75
  text "SURFACE FINISHED:" at 25048.5,19605.5 h75
  text "HASL(Pb-Free)" at 26378.5,19505.5 h75
  text "ENIG" at 27648.5,19505.5 h75
  text "OTHER" at 29238.5,19505.5 h75
  text "Common Tg" at 26255,19300 h75
  text "High Tg 180" at 27645,19300 h75
  text "High Tg 190" at 27645,19125 h75
  text "RCC Tg 150" at 26275,19100 h75
  text "PCB FR-4 Panel:" at 25075,19050 h75
  text "High Tg 170" at 26270,18925 h75
  text "High Tg 210" at 27645,18925 h75
  text "High Tg 175" at 26270,18750 h75
  text "CONTROL IMPEDANCE: YES" at 24938.5,18555.5 h75
  text "Pb LOGO: YES" at 27438.5,18555.5 h75
  text "B" at 8581.96,18546.31 h125
  text "B" at 8581.96,18546.31 h125
  text "B" at 31377.24,18546.31 h125
  text "B" at 31377.24,18546.31 h125
  text "SPELL MODE: 1 : 1" at 24938.5,18355.5 h75
  text "OPEN WINDOWS:  NO" at 27438.5,18355.5 h75
  text "OUTLINE PROFILE:ROUTER     BRIDGE   STAMP HOLE   V-CUT(ANGLE 30)" at 24938.5,18155.5 h75
  text "INSPECTION STANDARD:IPC-II      IPC-III      GB-4588      OTHER" at 24938.5,17955.5 h75
  text "VIA TECHNIC:ALL VIA FILLED           BY GERBER" at 24938.5,17755.5 h75
  text "PRESSFIT HOLES: NO                   YES(TOLERANCE+/-0.05mm)" at 24938.5,17555.5 h75
  text "BOW AND TWIST TOLERANCE:<=0.75%            Specify   %" at 24938.5,17355.5 h75
  text "DESIGN BY:KBPCB     E-MAIL:xxxxxx   TEL:0755-xxxxx" at 24938.5,17155.5 h75
  text "OTHER:" at 24938.5,16955.5 h75
  text "V-cut Detail:" at 27800,16775 h75
  text "MAX45" at 28300,16675 h50
  text "T" at 28575,16600 h50
  text "30" at 28301.1,16593 h50
  text "C" at 8593.5,16577.81 h125
  text "C" at 8593.5,16577.81 h125
  text "C" at 31388.78,16577.81 h125
  text "C" at 31388.78,16577.81 h125
  text "1/3T" at 28825,16525 h50
  text "MIN0.30mm MAX0.70mm" at 28825,16425 h50
  text "Impedance Control Table" at 26838.5,15435.5 h75
  text "SINGLE IMPEDANCE (+/-10)%" at 25378.5,15235.5 h75
  text "DIFF IMPEDANCE (+/-10%)" at 28338.5,15235.5 h75
  text "LAYER" at 24478.5,15035.5 h75
  text "IMPEDANCE" at 25158.5,15035.5 h75
  text "WIDTH" at 26078.5,15035.5 h75
  text "REF LAYER" at 26758.5,15035.5 h75
  text "IMPEDANCE" at 27558.5,15035.5 h75
  text "WIDTH" at 28478.5,15035.5 h75
  text "SPACE" at 29278.5,15035.5 h75
  text "REF LAYER" at 29958.5,15035.5 h75
  text "L1" at 24568.5,14855.5 h75
  text "50 OHM" at 25248.5,14855.5 h75
  text "6 Mil" at 26078.5,14855.5 h75
  text "100 OHM" at 27618.5,14855.5 h75
  text "5.5 Mil" at 28418.5,14855.5 h75
  text "9 Mil" at 29278.5,14855.5 h75
  text "L2" at 24568.5,14655.5 h75
  text "50 OHM" at 25248.5,14655.5 h75
  text "6 Mil" at 26078.5,14655.5 h75
  text "100 OHM" at 27618.5,14655.5 h75
  text "5.5 Mil" at 28418.5,14655.5 h75
  text "9 Mil" at 29278.5,14655.5 h75
  text "D" at 8577.48,14609.31 h125
  text "D" at 8577.48,14609.31 h125
  text "D" at 31372.75,14609.31 h125
  text "D" at 31372.75,14609.31 h125
  text "L3" at 24568.5,14455.5 h75
  text "50 OHM" at 25248.5,14455.5 h75
  text "6 Mil" at 26078.5,14455.5 h75
  text "100 OHM" at 27618.5,14455.5 h75
  text "5.5 Mil" at 28418.5,14455.5 h75
  text "9 Mil" at 29278.5,14455.5 h75
  text "L4" at 24568.5,14255.5 h75
  text "50 OHM" at 25248.5,14255.5 h75
  text "6 Mil" at 26078.5,14255.5 h75
  text "100 OHM" at 27618.5,14255.5 h75
  text "5.5 Mil" at 28418.5,14255.5 h75
  text "9 Mil" at 29278.5,14255.5 h75
  text "L5" at 24568.5,14055.5 h75
  text "50 OHM" at 25248.5,14055.5 h75
  text "6 Mil" at 26078.5,14055.5 h75
  text "100 OHM" at 27618.5,14055.5 h75
  text "5.5 Mil" at 28418.5,14055.5 h75
  text "9 Mil" at 29278.5,14055.5 h75
  text "L6" at 24568.5,13855.5 h75
  text "50 OHM" at 25248.5,13855.5 h75
  text "6 Mil" at 26078.5,13855.5 h75
  text "100 OHM" at 27618.5,13855.5 h75
  text "5.5 Mil" at 28418.5,13855.5 h75
  text "9 Mil" at 29278.5,13855.5 h75
  text "L7" at 24568.5,13655.5 h75
  text "50 OHM" at 25248.5,13655.5 h75
  text "6 Mil" at 26078.5,13655.5 h75
  text "100 OHM" at 27618.5,13655.5 h75
  text "5.5 Mil" at 28418.5,13655.5 h75
  text "9 Mil" at 29278.5,13655.5 h75
  text "L8" at 24568.5,13455.5 h75
  text "50 OHM" at 25248.5,13455.5 h75
  text "6 Mil" at 26078.5,13455.5 h75
  text "100 OHM" at 27618.5,13455.5 h75
  text "5.5 Mil" at 28418.5,13455.5 h75
  text "9 Mil" at 29278.5,13455.5 h75
  text "L9" at 24568.5,13255.5 h75
  text "50 OHM" at 25248.5,13255.5 h75
  text "6 Mil" at 26078.5,13255.5 h75
  text "100 OHM" at 27618.5,13255.5 h75
  text "5.5 Mil" at 28418.5,13255.5 h75
  text "9 Mil" at 29278.5,13255.5 h75
  text "L10" at 24538.5,13055.5 h75
  text "50 OHM" at 25248.5,13055.5 h75
  text "6 Mil" at 26078.5,13055.5 h75
  text "100 OHM" at 27618.5,13055.5 h75
  text "5.5 Mil" at 28418.5,13055.5 h75
  text "9 Mil" at 29278.5,13055.5 h75
  text "L11" at 24538.5,12855.5 h75
  text "50 OHM" at 25248.5,12855.5 h75
  text "6 Mil" at 26078.5,12855.5 h75
  text "100 OHM" at 27618.5,12855.5 h75
  text "5.5 Mil" at 28418.5,12855.5 h75
  text "9 Mil" at 29278.5,12855.5 h75
  text "L12" at 24538.5,12655.5 h75
  text "50 OHM" at 25248.5,12655.5 h75
  text "6 Mil" at 26078.5,12655.5 h75
  text "100 OHM" at 27618.5,12655.5 h75
  text "5.5 Mil" at 28418.5,12655.5 h75
  text "9 Mil" at 29278.5,12655.5 h75
  text "E" at 8589.83,12640.8 h125
  text "E" at 8589.83,12640.8 h125
  text "E" at 31385.11,12640.8 h125
  text "E" at 31385.11,12640.8 h125
  text "0.5 OZ   Layer1" at 29664.5,12134.5 h30
  text "Prepreg  3.9 MIl" at 25477.5,12034.5 h30
  text "0.5 OZ   Layer2" at 29664.5,11934.5 h30
  text "MCU V1 DRILL CHART" at 23075,11870 h100
  text "Core 5 MIl" at 25549.5,11834.5 h30
  text "0.5 OZ   Layer3" at 29664.5,11734.5 h30
  text "1--Gerber TOP" at 23075,11670 h100
  text "Prepreg 8 MIl" at 25513.5,11634.5 h30
  text "0.5 OZ   Layer4" at 29664.5,11534.5 h30
  text "2--Gerber BOTTOM" at 23075,11470 h100
  text "Core 5 MIl" at 25549.5,11434.5 h30
  text "0.5 OZ   Layer5" at 29664.5,11334.5 h30
  text "Prepreg 8 MIl" at 25513.5,11234.5 h30
  text "0.5 OZ   Layer6" at 29664.5,11134.5 h30
  text "Core 5 MIl" at 25549.5,11034.5 h30
  text "0.5 OZ   Layer7" at 29664.5,10934.5 h30
  text "Prepreg 8 MIl" at 25513.5,10834.5 h30
  text "0.5 OZ   Layer8" at 29664.5,10734.5 h30
  text "F" at 8589.83,10672.3 h125
  text "F" at 8589.83,10672.3 h125
  text "F" at 31385.11,10672.3 h125
  text "F" at 31385.11,10672.3 h125
  text "Core 5 MIl" at 25549.5,10634.5 h30
  text "0.5 OZ   Layer9" at 29664.5,10534.5 h30
  text "Prepreg 8 MIl" at 25513.5,10434.5 h30
  text "0.5 OZ   Layer10" at 29652.5,10334.5 h30
  text "Core 5 MIl" at 25549.5,10234.5 h30
  text "0.5 OZ   Layer11" at 29652.5,10134.5 h30
  text "Prepreg  3.9 MIl" at 25477.5,10034.5 h30
  text "0.5 OZ   Layer12" at 29652.5,9934.5 h30
  text "G" at 8586.04,8703.8 h125
  text "G" at 8586.04,8703.8 h125
  text "G" at 31381.31,8703.8 h125
  text "G" at 31381.31,8703.8 h125
  text "Revision:" at 27000,6800 h90
  text "Data:" at 28100,6800 h90
  text "Designer:" at 29050,6800 h90
  text "QA:" at 30200,6800 h90
  text "H" at 8581.96,6735.3 h125
  text "H" at 8581.96,6735.3 h125
  text "H" at 31377.24,6735.3 h125
  text "H" at 31377.24,6735.3 h125
  text "1.0" at 27275,6600 h90
  text "2011-01-01" at 28100,6600 h90
  text "KBPCB010" at 29075,6600 h90
  text "KBPCB001" at 30175,6600 h90
  text "3" at 15747.01,5577.13 h125
  text "3" at 15747.01,5577.13 h125
  text "5" at 21396.61,5577.14 h125
  text "5" at 21396.61,5577.14 h125
  text "1" at 10116.41,5573.87 h125
  text "1" at 10116.41,5573.87 h125
  text "4" at 18567.2,5573.88 h125
  text "4" at 18567.2,5573.88 h125
  text "7" at 27049.48,5573.87 h125
  text "7" at 27049.48,5573.87 h125
  text "8" at 29874.28,5573.87 h125
  text "8" at 29874.28,5573.87 h125
  text "2" at 12922.74,5569.93 h125
  text "2" at 12922.74,5569.93 h125
  text "6" at 24225.48,5570.34 h125
  text "6" at 24225.48,5570.34 h125
OUTLINE:
  lines w1: 12000,10100 ccw(c12100,10100) 12100,10000 16230.71,10000 ccw(c16230.71,10100) 16330.71,10100 16330.71,12262.2 ccw(c16230.71,12262.2) 16230.71,12362.2 12100,12362.2 ccw(c12100,12262.2) 12000,12262.2 12000,10100
PIN_NUMBER:
  text "1" at 12461.8,12200 h33
  text "1" at 12461.8,10150 h33
  text "1" at 15861.8,10150 h33
PLACE_BOUND_TOP:
  lines w1: 12455,10130 12455,10170 12495,10170 12495,10130 12455,10130 ; 12455,12180 12455,12220 12495,12220 12495,12180 12455,12180 ; 15855,10130 15855,10170 15895,10170 15895,10130 15855,10130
